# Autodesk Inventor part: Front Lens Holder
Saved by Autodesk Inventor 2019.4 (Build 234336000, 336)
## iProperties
Created: 2020-09
Part Number: Front Lens Holder
Material: Generic
Document SubType Name: Modeling
Designer: Administrator
Density: 1 g/cm^3
Appearance: Default
Title: Front Lens Holder
Author: Administrator
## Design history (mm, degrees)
feature "Body1"
body "Solid1"
